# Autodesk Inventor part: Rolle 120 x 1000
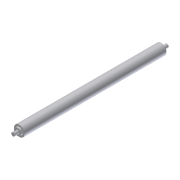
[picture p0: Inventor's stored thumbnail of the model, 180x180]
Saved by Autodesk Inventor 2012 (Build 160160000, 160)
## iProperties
Created: 2004-04
Part Number: Rolle 120 x 1000
Document SubType Name: Modeling
Manufacturer: Standard
Standards Organization: Custom
Description: Welle
Density: 1 g/cm^3
Material: Standard
Company: CAD-Verlag
+MSCProtocol1+ProtocolID: P00061127083254156
+MSCProtocol2+Protocol: P00061127083254156<@PID>[Version]<@EL>Version=2.0<@EL>[Mechsoft]<@EL>Dynamic=1<@EL>[Synchronize]<@EL>ChangedVars=<@EL>[Debug]<@EL>ChangedVars=<@EL>[Files]<@EL>D
Author: Jürgen Kronas
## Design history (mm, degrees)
sketch "Skizze2"
  geometry: L1 (0, 0)-(1735, 0) reference; L2 (0, 0)-(0, 20); L3 (0, 20)-(50, 20); L4 (50, 20)-(50, 40); L5 (50, 40)-(70, 40); L6 (70, 40)-(70, 60); L7 (1670, 60)-(1670, 40); L8 (70, 60)-(1670, 60); L9 (1685, 40)-(1685, 20); L10 (1670, 40)-(1685, 40); L11 (1735, 20)-(1735, 0); L12 (1685, 20)-(1735, 20)
  constraints: 24 end point, 6 vertical, 2 horizontal
  dimensions: "d0" = 40 diameter of L3 L1 (derived); "d1" = 80 diameter of L5 L1 (derived); "d2" = 120 diameter of L8 L1 (derived); "d3" = 80 diameter of L10 L1 (derived); "d4" = 40 diameter of L12 L1 (derived)
revolve "Drehung1" sketch "Skizze2" stored, may be unused: angle "d5" = 0 deg
feature "Keyway1"
feature "RRGroove1"
node "Volumenkörper1"
node "Volumenkörpern"
node "Oberflächenkörpern"
